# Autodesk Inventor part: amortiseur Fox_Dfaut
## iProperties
Created: 2006-03
Part Number: amortiseur Fox_Dfaut
Document SubType Name: Modeling
Designer: Flavien MARTY
Author: Flavien MARTY
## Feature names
1. Base1
